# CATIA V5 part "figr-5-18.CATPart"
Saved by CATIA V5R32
Part number: Part1
Bounding box of the stored display mesh (mm): x -50 to 50, y -70 to 70, z -20 to 40
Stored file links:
  D:\PROJECTS\Project 2022\CATIA V5 6R 2022\Resources\Part Files\c05_catia_v5_6r2022_prt\figr-5-18.CATPart
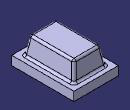
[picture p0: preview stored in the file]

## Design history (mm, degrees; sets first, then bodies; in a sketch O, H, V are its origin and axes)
Body1 (main body)
  Sketch1 on xy-plane, origin (0, 0, 0), H (1, 0, 0), V (0, 1, 0)
    line L1 (50, 70) -> (50, -70)
    line L2 (50, -70) -> (-50, -70)
    line L3 (-50, -70) -> (-50, 70)
    line L4 (-50, 70) -> (50, 70)
    length L2 = 100
    length L1 = 140
    vertical: L1 V, L3 V
    horizontal: L2 H, L4 H
    equidistance: L1 L3 O, L2 L4 O
  Pad1: profile Sketch1, direction (0, 0, -1), length 20
  Sketch2 on face of Pad1, origin (0, 0, 0), H (1, 0, 0), V (0, 1, 0)
    line L1 (30, 50) -> (30, -50)
    line L2 (30, -50) -> (-30, -50)
    line L3 (-30, -50) -> (-30, 50)
    line L4 (-30, 50) -> (30, 50)
    length L2 = 60
    length L1 = 100
    vertical: L1 V, L3 V
    horizontal: L2 H, L4 H
    equidistance: L1 L3 O, L2 L4 O
  Pad2: profile Sketch2, direction (0, 0, 1), length 40, opposite side up to face of Pad1
  Draft1: Angle 9, Neutral face of Pad2, PullDir face of Pad2, SupportToDraft (face of Pad2; face of Pad2; face of Pad2; face of Pad2)
  Fillet1: radius 5, on edge [face of Pad2 | face of Pad2] (x4)
  Fillet2: radius 5, on edge [face of Pad2 | face of Pad2] (x4)
  Fillet3: radius 5, on edge [face of Pad2 | face of Pad1] (x4)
